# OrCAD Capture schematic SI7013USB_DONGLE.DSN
size B; title: Si7013USB-Dongle; rev: 1.0; note: Si7013USB-Dongle
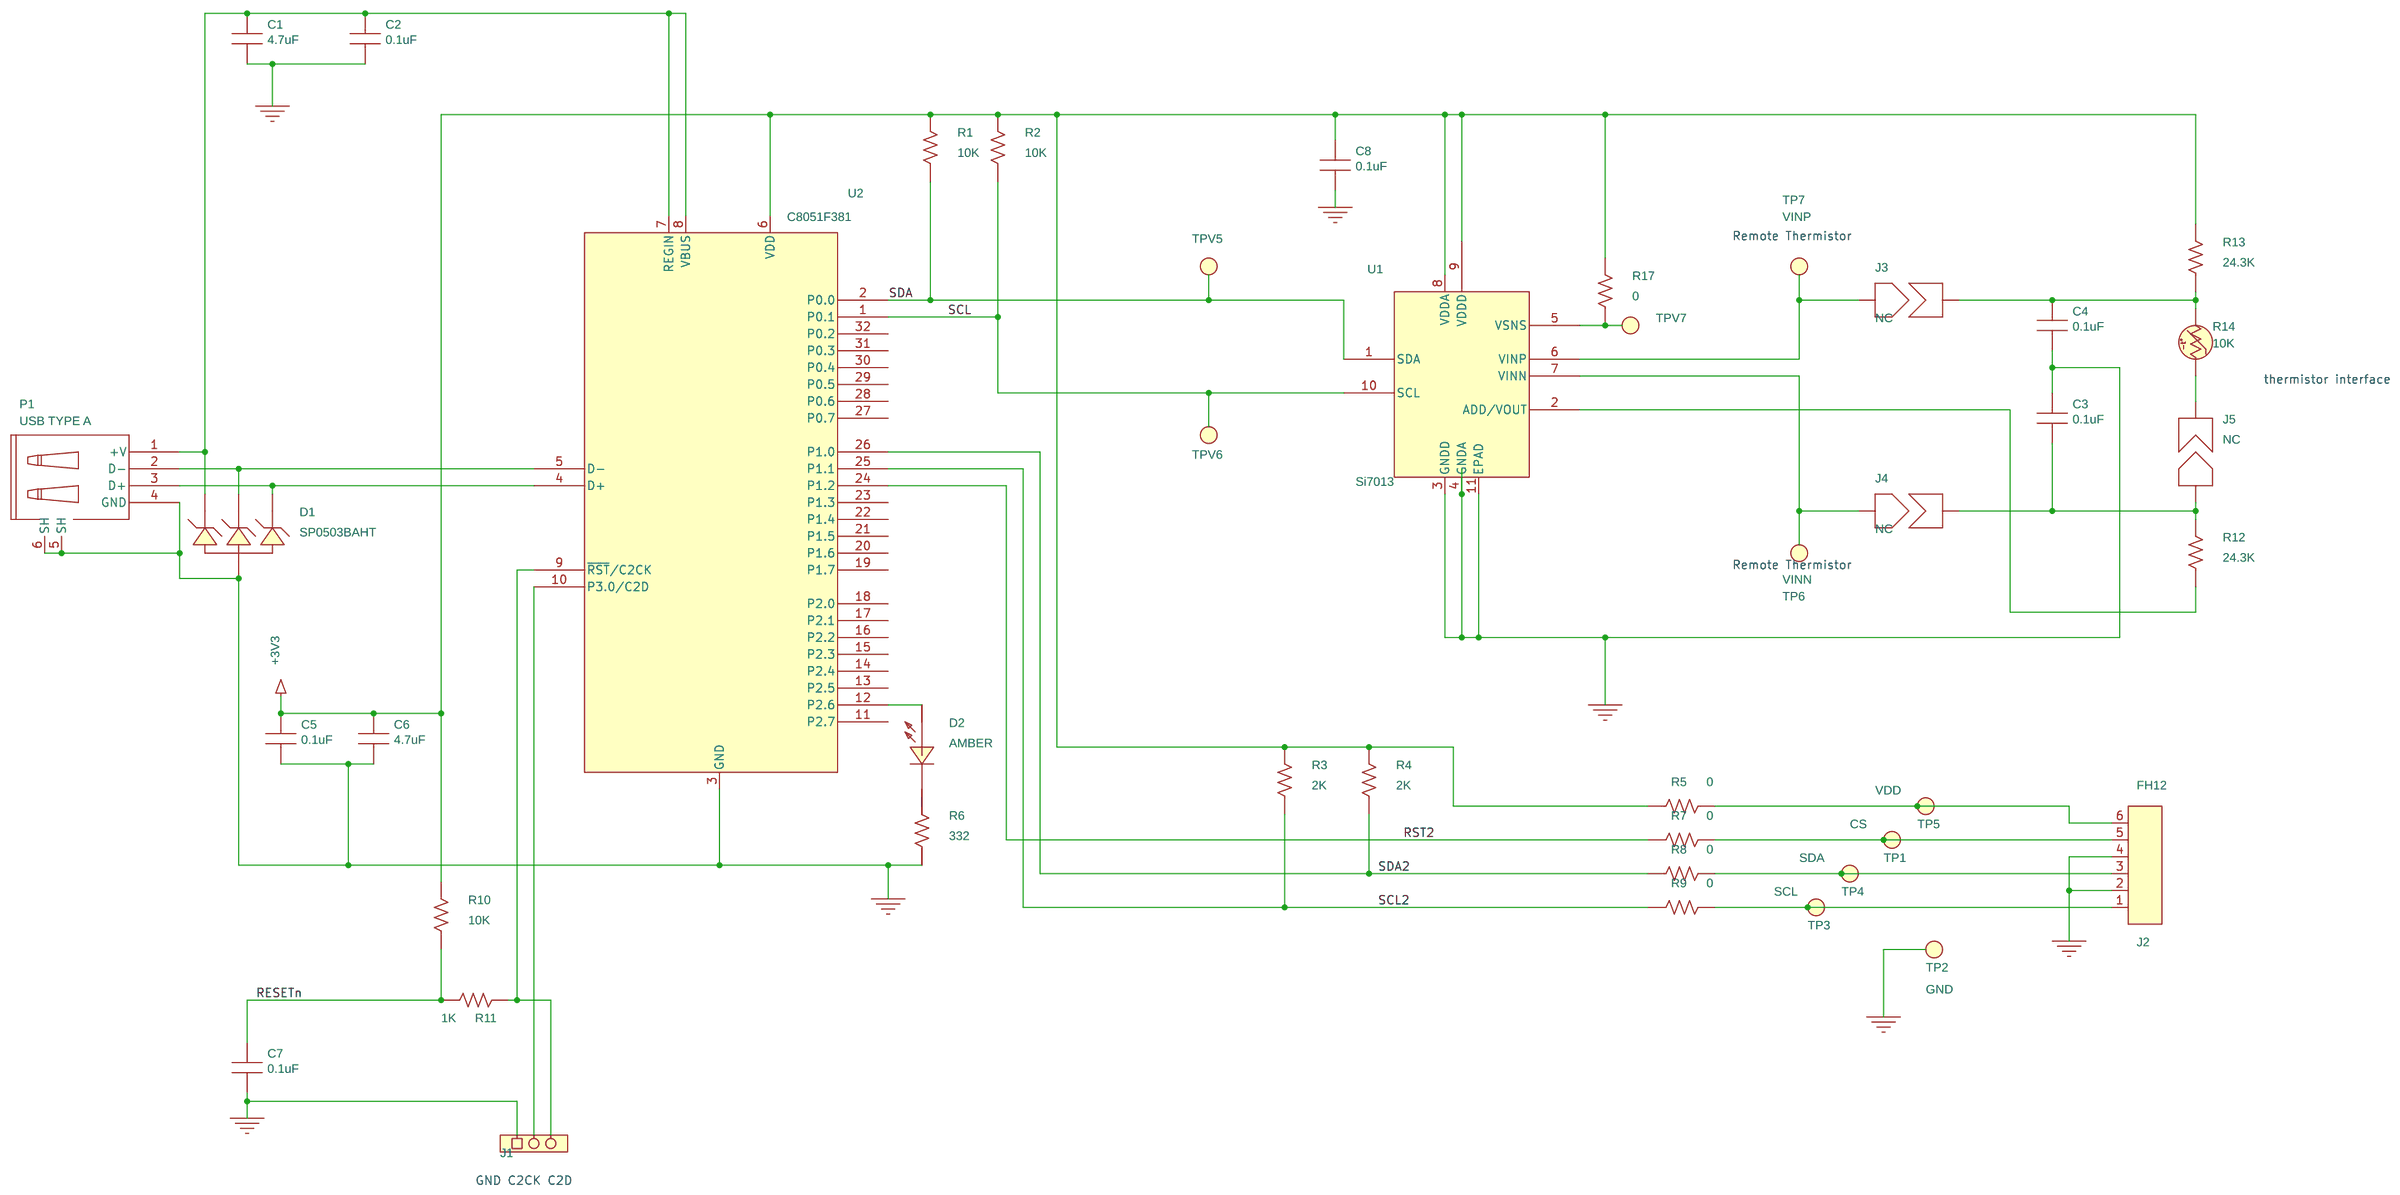
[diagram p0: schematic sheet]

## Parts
C1  4.7uF  [C0603]
C2  0.1uF  [C0402]
C3  0.1uF  [C0402]
C4  0.1uF  [C0402]
C5  0.1uF  [C0402]
C6  4.7uF  [C0603]
C7  0.1uF  [C0402]
C8  0.1uF  [C0402]
D1  SP0503BAHT  [SOT143-AKKK]
D2  AMBER  [LED-HSMX-C170]
J1  HEADER 1x3  [CONN-1X3]
J2  FH12  [CONN6N-FPC/FFC-P0.5]
J3  NC  [SB0402-NC]
J4  NC  [SB0402-NC]
J5  NC  [SB0402-NC]
P1  USB TYPE A  [USB_A_RA_SMT]
R1  10K  [R0402]
R2  10K  [R0402]
R3  2K  [R0402]
R4  2K  [R0402]
R5  0  [R0402]
R6  332  [R0402]
R7  0  [R0402]
R8  0  [R0402]
R9  0  [R0402]
R10  10K  [R0402]
R11  1K  [R0402]
R12  24.3K  [R0603]
R13  24.3K  [R0603]
R14  10K  [R0603]
R17  0  [R0402]
TP1  TPV  [VIA-TP]
TP2  TPV  [VIA-TP]
TP3  TPV  [VIA-TP]
TP4  TPV  [VIA-TP]
TP5  TPV  [VIA-TP]
TP6  BLACK  [TESTPOINT]
TP7  BLACK  [TESTPOINT]
TPV5  TPV  [VIA-TP]
TPV6  TPV  [VIA-TP]
TPV7  TPV  [VIA-TP]
U1  Si7013  [DFN10M3X3P0.5E1.4X2.6]
U2  C8051F381  [QFN32N5X5P0.5]

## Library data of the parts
C1 C6 = CAP_NP: CAP, 4.7uF, 6.3V, ±10%, X5R, 0603; Manufacturer: Venkel; ManufacturerPN: C0603X5R6R3-475K; Part_Type: CAP/NP; SiLabsPN: C0603X5R6R3-475K; Tolerance: ±10%; Type: X5R; Voltage: 6.3V; Datasheet: PID_C.pdf
C2 C5 C7 = CAP_NP: CAP, 0.1uF, 16V, ±20%, X7R, 0402; Manufacturer: Venkel; ManufacturerPN: C0402X7R160-104M; Part_Type: CAP/NP; SiLabsPN: C0402X7R160-104M; Tolerance: ±20%; Type: X7R; Voltage: 16V; Datasheet: PID_C.pdf
C3 C4 C8 = CAP_NP: CAP, 0.1uF, 10V, ±20%, X7R, 0402; Manufacturer: Venkel; ManufacturerPN: C0402X7R100-104M; SiLabsPN: C0402X7R100-104M; Tolerance: ±20%; Type: X7R; Voltage: 10V; Datasheet: PID_C.pdf
D1 = ZENER_TRIPLE_COM_ANODE: Diode Array, TVS Avalanche; Manufacturer: Littlefuse; ManufacturerPN: SP0503BAHTG; Part_Type: PROT/FIXED; Rating: 300mW; SiLabsPN: SP0503BAHTG; Type: TVS; Voltage: 20V; Datasheet: SP05xxBA.pdf
D2 = LED: LED, Amber, AllnGaP, 20mA, 60mW, 90mcd, 0805; Manufacturer: Avago Technologies; ManufacturerPN: HSMA-C170; Part_Type: OPTO/LED; Rating: 25mA; SiLabsPN: HSMA-C170; Type: SMT, ChipLED; Voltage: 1.9V; Datasheet: AV02-0112EN-1.pdf
J1 = HEADER_1X3: Header, 3x1, 0.1in pitch, Tin Plated; Manufacturer: Samtec; ManufacturerPN: TSW-103-07-T-S; SiLabsPN: TSW-103-07-T-S; Type: Header; Datasheet: TSW_TH.PDF
J2 = CON6: CONN, 6-PIN , FPC/FFC, BOTTOM CONTACT, 0.5MM PITCH, SMD; Manufacturer: HIROSE; ManufacturerPN: FH12-6S-0.5SH(55); Part_Type: CON/MODULAR; SiLabsPN: FH12-6S-0.5SH(55); Datasheet: e58605370.pdf
J3-J5 = SolderBump: SOLDER BUMP JUMPER, NC, 0402; Manufacturer: N/A; ManufacturerPN: N/A; Type: PCB Feature
P1 = CN-USB: CONN, USB TYPE A 4P, RIGHT ANGLE, SMT; Manufacturer: Molex; ManufacturerPN: 48037-1000; Part_Type: CON; SiLabsPN: 48037-1000; Type: USB; Datasheet: 480371000_sd.pdf
R1 R2 = RES: RES, 10K, 1/16W, ±1%, ThickFilm, 0402; Manufacturer: Venkel; ManufacturerPN: CR0402-16W-1002F; Rating: 1/16W; SiLabsPN: CR0402-16W-1002F; Tolerance: ±1%; Type: ThickFilm; Datasheet: PID_CR.pdf
R3 R4 = RES: RES, 2K, 1/16W, ±1%, ThickFilm, 0402; Manufacturer: Venkel; ManufacturerPN: CR0402-16W-2001F; Rating: 1/16W; SiLabsPN: CR0402-16W-2001F; Tolerance: ±1%; Type: ThickFilm; Datasheet: PID_CR.pdf
R5 R7-R9 R17 = RES: RES, 0 Ohm, 1A, ThickFilm, 0402; Manufacturer: Venkel; ManufacturerPN: CR0402-16W-000; Rating: 1A; SiLabsPN: CR0402-16W-000; Type: ThickFilm; Datasheet: PID_CR.pdf
R6 = RES: RES, 332 Ohm, 1/16W, ±1%, ThickFilm, 0402; Manufacturer: Venkel; ManufacturerPN: CR0402-16W-3320F; Part_Type: RES/SMT; Rating: 1/16W; SiLabsPN: CR0402-16W-3320F; Tolerance: ±1%; Type: ThickFilm; Datasheet: PID_CR.pdf
R10 = RES: RES, 10K, 1/16W, ±1%, ThickFilm, 0402; Manufacturer: Venkel; ManufacturerPN: CR0402-16W-1002F; Part_Type: RES/SMT; Rating: 1/16W; SiLabsPN: CR0402-16W-1002F; Tolerance: ±1%; Type: ThickFilm; Datasheet: PID_CR.pdf
R11 = RES: RES, 1K, 1/16W, ±1%, ThickFilm, 0402; Manufacturer: Venkel; ManufacturerPN: CR0402-16W-1001F; Part_Type: RES/SMT; Rating: 1/16W; SiLabsPN: CR0402-16W-1001F; Tolerance: ±1%; Type: ThickFilm; Datasheet: PID_CR.pdf
R12 R13 = RES: RES, 24.3K, 1/16W, ±1%, ThickFilm, 0603; Manufacturer: Venkel; ManufacturerPN: CR0603-16W-2432F; Rating: 1/16W; SiLabsPN: CR0603-16W-2432F; Tolerance: ±1%; Type: ThickFilm; Datasheet: PID_CR.pdf
R14 = Thermistor: Thermistor, 10K, ±1%, 0603; Manufacturer: Murata; ManufacturerPN: NCP18XH103F03RB; SiLabsPN: NCP18XH103F03RB; Tolerance: ±1%; Type: NTC; Datasheet: r44e.pdf
TP1 = TPV: TESTPOINT Via; Manufacturer: N/A; ManufacturerPN: N/A; Silk: CS; Type: PCB Feature
TP2 = TPV: TESTPOINT Via; Manufacturer: N/A; ManufacturerPN: N/A; Silk: GND; Type: PCB Feature
TP3 = TPV: TESTPOINT Via; Manufacturer: N/A; ManufacturerPN: N/A; Silk: SCL; Type: PCB Feature
TP4 = TPV: TESTPOINT Via; Manufacturer: N/A; ManufacturerPN: N/A; Silk: SDA; Type: PCB Feature
TP5 = TPV: TESTPOINT Via; Manufacturer: N/A; ManufacturerPN: N/A; Silk: VDD; Type: PCB Feature
TP6 = TEST_POINT: TESTPOINT, BLACK, PTH; Manufacturer: Kobiconn; ManufacturerPN: 151-203-RC; SiLabsPN: 151-203; Silk: VINN; Type: Loop; Datasheet: KC-300780.pdf
TP7 = TEST_POINT: TESTPOINT, BLACK, PTH; Manufacturer: Kobiconn; ManufacturerPN: 151-203-RC; SiLabsPN: 151-203; Silk: VINP; Type: Loop; Datasheet: KC-300780.pdf
TPV5-TPV7 = TPV: TESTPOINT Via; Manufacturer: N/A; ManufacturerPN: N/A; Type: PCB Feature
U1 = SI7013: IC, SENSOR, HUMIDITY, DFN10; Manufacturer: SiLabs; ManufacturerPN: Si7013-A-GM; SiLabsPN: TMP-2779; Type: Sensor; Voltage: +4.2V; Datasheet: Si7013 Rev 0 2 draft 3 5 2013.pdf
U2 = C8051F342QFN32: IC, 8051 MCU FLASH 64K, QFN32; Manufacturer: SiLabs; ManufacturerPN: C8051F381-GM; SiLabsPN: C8051F381-GM; Type: MCU; Datasheet: C8051F38x.pdf

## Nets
+3V3: C5.1 C6.1 C8.1 R1.2 R2.2 R3.2 R4.2 R5.1 R10.2 R13.2 R17.2 U1.8(VDDA) U1.9(VDDD) U2.6(VDD)
GND: C1.2 C2.2 C3.1 C4.2 C5.2 C6.2 C7.2 C8.2 D1.A(ANODE) J1.1 J2.2 J2.4 P1.4(GND) P1.5(SH) P1.6(SH) R6.1 TP2.1(Point) U1.3(GNDD) U1.4(GNDA) U1.11(EPAD) U2.3(GND)
RESETn: C7.1 R10.1 R11.1
RST2: R7.1 U2.24(P1.2)
SCL: R2.1 TPV6.1(Point) U1.10(SCL) U2.1(P0.1)
SCL2: R3.1 R9.1 U2.25(P1.1)
SDA: R1.1 TPV5.1(Point) U1.1(SDA) U2.2(P0.0)
SDA2: R4.1 R8.1 U2.26(P1.0)
N00193: D1.K2(CATHODE) P1.2(D-) U2.5(D-)
N00209: C1.1 C2.1 D1.K3(CATHODE) P1.1(+V) U2.7(REGIN) U2.8(VBUS)
N16430134: D2.K(CATHODE) R6.2
N16467617: D1.K1(CATHODE) P1.3(D+) U2.4(D+)
N16528682: D2.A(ANODE) U2.12(P2.6)
N16530649: J2.5 R7.2 TP1.1(Point)
N16597447: J1.3 R11.2 U2.9(~{RST}/C2CK)
N16656669: J2.1 R9.2 TP3.1(Point)
N16670007: J2.3 R8.2 TP4.1(Point)
N16779706: J2.6 R5.2 TP5.1(Point)
N16788910: J1.2 U2.10(P3.0/C2D)
N16801374: C4.1 J3.2(IO2) R13.1 R14.2
N16801376: C3.2 J4.2(IO2) J5.1(IO1) R12.2
N16801435: J5.2(IO2) R14.1
N16801437: R12.1 U1.2(ADD/VOUT)
N16801515: R17.1 TPV7.1(Point) U1.5(VSNS)
N16804011: J3.1(IO1) TP7.1(Point) U1.6(VINP)
N16804024: J4.1(IO1) TP6.1(Point) U1.7(VINN)

Not connected (* = marked no-connect by the designer): U2 11(P2.7) 13(P2.5) 14(P2.4) 15(P2.3) 16(P2.2) 17(P2.1) 18(P2.0) 19(P1.7) 20(P1.6) 21(P1.5) 22(P1.4) 23(P1.3) 27(P0.7) 28(P0.6) 29(P0.5) 30(P0.4) 31(P0.3) 32(P0.2)

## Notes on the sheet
- Remote Thermistor
- thermistor interface
- Remote Thermistor
- GND C2CK C2D
